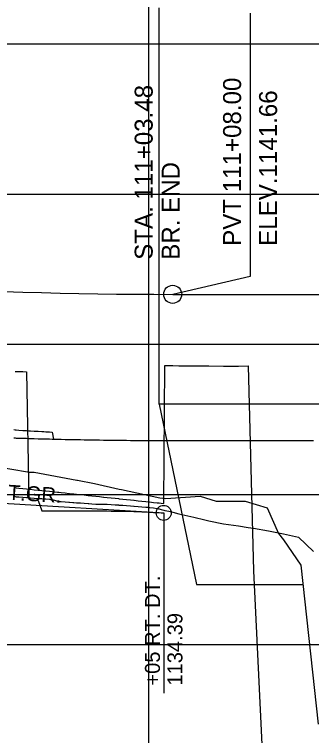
# Model space of a CAD drawing. Extents: x 688474 to 694748, y 765018 to 767373.
# Drawn here: x 692008.8 to 692107.9, y 765929.6 to 766169.7 of the extents above; entities that cross this region are included whole.
import ezdxf

# ---------------------------------------------------------------- set-up
doc = ezdxf.new("R2010")
doc.units = 0
for name, color, linetype in [('37', 7, 'Continuous'), ('BRIDGE', 7, 'Continuous'), ('R_Exist Surface', 7, 'Continuous'), ('R_Profile Work Left', 7, 'Continuous'), ('R_Profile Work Right', 7, 'Continuous'), ('R_Vert Alg', 7, 'Continuous'), ('R_Vert Alg Annot', 7, 'Continuous')]:
    doc.layers.add(name, color=color, linetype=linetype)

msp = doc.modelspace()

# ---------------------------------------------------------------- linework, layer by layer
at = {"layer": '37'}
for p, q in [((692053.59, 765809.92), (692053.59, 766359.92)), ((690853.59, 766159.92), (693453.59, 766159.92)), ((690853.59, 766109.92), (693453.59, 766109.92)), ((690853.59, 766059.92), (693453.59, 766059.92)), ((690853.59, 766009.92), (693453.59, 766009.92)), ((690853.59, 765959.92), (693453.59, 765959.92))]:
    msp.add_line(p, q, dxfattribs=at)
at = {"layer": 'BRIDGE'}
for p, q in [((692057.07, 766076.54), (692057.07, 766171.9)), ((692057.07, 766039.94), (692057.07, 766076.54)), ((692308.1, 766039.92), (692057.07, 766039.94)), ((692057.07, 766039.93), (692069.49, 765979.92)), ((692069.49, 765979.92), (692104.99, 765979.92))]:
    msp.add_line(p, q, dxfattribs=at)
at = {"layer": 'R_Exist Surface'}
msp.add_lwpolyline([(692000.61, 766019.59), (692013.83, 766017.31), (692015.39, 766017.32), (692029.58, 766014.68), (692029.87, 766014.67), (692035.49, 766013.58), (692043.77, 766011.69), (692044.49, 766011.59), (692057.34, 766008.76), (692059.3, 766008.51), (692070.73, 766009.33), (692076.14, 766007.7), (692085.77, 766007.66), (692093.07, 766005.48), (692096.83, 765996.91), (692098.54, 765994.77), (692104.27, 765986.41), (692110.15, 765933.44)], dxfattribs=at)
at = {"layer": 'R_Profile Work Left'}
for points in [[(692008.59, 766031.54), (692009.02, 766031.46), (692009.35, 766031.39), (692010.31, 766031.33), (692011.59, 766031.25), (692012.87, 766031.17), (692013.59, 766031.12), (692014.15, 766031.09), (692015.43, 766031.01), (692016.72, 766030.93), (692018, 766030.85), (692018.59, 766030.82), (692019.28, 766030.78), (692020.56, 766030.7), (692021.44, 766030.65), (692021.84, 766028.34), (692023.13, 766028.31), (692023.59, 766028.3), (692024.41, 766028.28), (692025.69, 766028.25), (692026.97, 766028.22), (692027.16, 766028.22), (692028.25, 766028.2), (692028.59, 766028.19), (692029.54, 766028.17), (692030.82, 766028.15), (692032.1, 766028.12), (692033.38, 766028.1), (692033.59, 766028.1), (692034.67, 766028.08), (692035.95, 766028.06), (692037.23, 766028.04), (692038.51, 766028.02), (692038.59, 766028.02), (692039.79, 766028), (692041.08, 766027.98), (692042.36, 766027.97), (692043.59, 766027.95), (692043.64, 766027.95), (692044.92, 766027.94), (692046.2, 766027.93), (692047.49, 766027.91), (692048.59, 766027.91), (692048.77, 766027.9), (692050.05, 766027.89), (692051.33, 766027.89), (692052.61, 766027.88), (692053.59, 766027.87), (692053.9, 766027.87), (692055.18, 766027.87), (692056.46, 766027.86), (692056.89, 766027.86), (692057.07, 766027.86), (692057.74, 766027.86), (692058.59, 766027.86), (692059.02, 766027.86), (692060.31, 766027.85), (692061.59, 766027.85), (692063.59, 766027.85), (692068.59, 766027.85), (692069.57, 766027.85), (692071.44, 766027.85), (692073.59, 766027.85), (692078.59, 766027.85), (692083.59, 766027.85), (692086.74, 766027.85), (692088.59, 766027.85), (692093.59, 766027.85), (692098.59, 766027.85), (692103.59, 766027.85), (692108.59, 766027.85)], [(692008.59, 766009.22), (692009.02, 766009.19), (692009.35, 766009.17), (692010.31, 766009.09), (692011.59, 766009), (692012.87, 766008.9), (692013.59, 766008.85), (692014.15, 766008.8), (692015.43, 766008.7), (692016.72, 766008.61), (692018, 766008.51), (692018.59, 766008.46), (692019.28, 766008.41), (692020.56, 766008.31), (692021.44, 766008.02), (692021.84, 766008.07), (692023.13, 766007.62), (692023.59, 766007.59), (692024.41, 766007.53), (692025.69, 766007.44), (692026.97, 766007.34), (692027.16, 766007.33), (692028.25, 766007.25), (692028.59, 766007.23), (692029.54, 766007.16), (692030.82, 766007.07), (692032.1, 766006.98), (692033.38, 766006.88), (692033.59, 766006.87), (692034.67, 766006.79), (692035.95, 766006.7), (692037.23, 766006.63), (692038.51, 766006.68), (692038.59, 766006.68), (692039.79, 766006.68), (692041.08, 766006.59), (692042.36, 766006.49), (692043.59, 766006.4), (692043.64, 766006.39), (692044.92, 766006.3), (692046.2, 766006.2), (692047.49, 766006.1), (692048.59, 766006.02), (692048.77, 766006), (692050.05, 766005.91), (692051.33, 766005.81), (692052.61, 766005.71), (692053.59, 766005.64), (692053.9, 766005.61), (692055.18, 766005.41), (692056.46, 766005.2), (692056.89, 766005.12), (692057.07, 766005.08), (692057.74, 766004.92), (692058.59, 766004.71), (692059.02, 766004.61), (692060.31, 766004.3), (692061.59, 766003.99), (692063.59, 766003.51), (692068.59, 766002.31), (692069.57, 766002.08), (692071.44, 766001.63), (692073.59, 766001.11), (692078.59, 766000.13), (692083.59, 765999.41), (692086.74, 765998.96), (692088.59, 765998.69), (692093.59, 765997.84), (692098.59, 765996.77), (692103.59, 765995.69), (692108.59, 765990.88)]]:
    msp.add_lwpolyline(points, dxfattribs=at)
at = {"layer": 'R_Profile Work Right'}
for points in [[(692058.59, 766006.92), (692059.02, 766052.81), (692060.31, 766052.8), (692061.59, 766052.79), (692063.59, 766052.77), (692068.59, 766052.73), (692069.57, 766052.72), (692071.44, 766052.7), (692073.59, 766052.69), (692078.59, 766052.65), (692083.59, 766052.64), (692086.74, 766052.68)], [(692086.74, 766052.68), (692088.59, 765984.46), (692093.59, 765880.56), (692098.59, 765883.29), (692103.59, 765885.82), (692108.59, 765887.81)], [(692009.02, 766050.87), (692009.35, 766050.86), (692010.31, 766050.84), (692011.59, 766050.8), (692012.87, 766050.77), (692013.59, 766008.3), (692014.15, 766008.22), (692015.43, 766008.07), (692016.72, 766007.92), (692018, 766004.41), (692018.59, 766004.41), (692019.28, 766004.41), (692020.56, 766004.42), (692021.44, 766004.42), (692021.84, 766004.42), (692023.13, 766004.42), (692023.59, 766004.43), (692024.41, 766004.45), (692025.69, 766004.45), (692026.97, 766004.46), (692027.16, 766004.46), (692028.25, 766004.47), (692028.59, 766004.47), (692029.54, 766004.47), (692030.82, 766004.48), (692032.1, 766004.48), (692033.38, 766004.51), (692033.59, 766004.51), (692034.67, 766004.5), (692035.95, 766004.48), (692037.23, 766004.46), (692038.51, 766004.44), (692038.59, 766004.44), (692039.79, 766004.42), (692041.08, 766004.4), (692042.36, 766004.39), (692043.59, 766004.37), (692043.64, 766004.37), (692044.92, 766004.35), (692046.2, 766004.33), (692047.49, 766004.31), (692048.59, 766004.26), (692048.77, 766004.25), (692050.05, 766004.19), (692051.33, 766004.14), (692052.61, 766004.08), (692053.59, 766004.03), (692053.9, 766004.02), (692055.18, 766003.95), (692056.46, 766003.89), (692056.89, 766003.86), (692057.07, 766003.85), (692057.74, 766003.82), (692058.59, 766003.78)], [(692008.59, 766028.72), (692009.02, 766028.71), (692009.35, 766028.7), (692010.31, 766028.66), (692011.59, 766028.62), (692012.87, 766028.59), (692013.59, 766028.56), (692014.15, 766028.55), (692015.43, 766028.51), (692016.72, 766028.47), (692018, 766028.44), (692018.59, 766028.42), (692019.28, 766028.41), (692020.56, 766028.37), (692021.44, 766028.35), (692021.84, 766028.34), (692023.13, 766028.31), (692023.59, 766028.3), (692024.41, 766028.28), (692025.69, 766028.25), (692026.97, 766028.22), (692027.16, 766028.22), (692028.25, 766028.2), (692028.59, 766028.19), (692029.54, 766028.17), (692030.82, 766028.15), (692032.1, 766028.12), (692033.38, 766028.1), (692033.59, 766028.09), (692034.67, 766028.08), (692035.95, 766028.06), (692037.23, 766028.04), (692038.51, 766028.02), (692038.59, 766028.02), (692039.79, 766028), (692041.08, 766027.98), (692042.36, 766027.97), (692043.59, 766027.95), (692043.64, 766027.95), (692044.92, 766027.94), (692046.2, 766027.93), (692047.49, 766027.91), (692048.59, 766027.9), (692048.77, 766027.9), (692050.05, 766027.89), (692051.33, 766027.89), (692052.61, 766027.88), (692053.59, 766027.87), (692053.9, 766027.87), (692055.18, 766027.87), (692056.46, 766027.86), (692056.89, 766027.86), (692057.07, 766027.86), (692057.74, 766027.86), (692058.59, 766027.86), (692059.02, 766027.85), (692060.31, 766027.85), (692061.59, 766027.85), (692063.59, 766027.85), (692068.59, 766027.85), (692069.57, 766027.85), (692071.44, 766027.85), (692073.59, 766027.85), (692078.59, 766027.85), (692083.59, 766027.85), (692086.74, 766027.85), (692088.59, 766027.85), (692093.59, 766027.85), (692098.59, 766027.85), (692103.59, 766027.85), (692108.59, 766027.85)], [(692009.02, 766012.17), (692009.35, 766012.14), (692010.31, 766012.04), (692011.59, 766011.9), (692012.87, 766011.77), (692013.59, 766011.69), (692014.15, 766011.63), (692015.43, 766011.49), (692016.72, 766011.36), (692018, 766011.22), (692018.59, 766011.16), (692019.28, 766011.09), (692020.56, 766010.95), (692021.44, 766010.86), (692021.84, 766010.81), (692023.13, 766010.68), (692023.59, 766010.63), (692024.41, 766010.54), (692025.69, 766010.41), (692026.97, 766010.27), (692027.16, 766010.25), (692028.25, 766010.14), (692028.59, 766010.1), (692029.54, 766010), (692030.82, 766009.86), (692032.1, 766009.73), (692033.38, 766009.59), (692033.59, 766009.57), (692034.67, 766009.46), (692035.95, 766009.32), (692037.23, 766009.18), (692038.51, 766009.05), (692038.59, 766009.04), (692039.79, 766008.91), (692041.08, 766008.78), (692042.36, 766008.64), (692043.59, 766008.51), (692043.64, 766008.5), (692044.92, 766008.37), (692046.2, 766008.23), (692047.49, 766008.1), (692048.59, 766007.98), (692048.77, 766007.96), (692050.05, 766007.83), (692051.33, 766007.69), (692052.61, 766007.55), (692053.59, 766007.45), (692053.9, 766007.42), (692055.18, 766007.28), (692056.46, 766007.15), (692056.89, 766007.1), (692057.07, 766007.08), (692057.74, 766007.01), (692058.59, 766006.92)]]:
    msp.add_lwpolyline(points, dxfattribs=at)
at = {"layer": 'R_Vert Alg'}
for p, q in [((692061.59, 766076.52), (692343.59, 766076.52)), ((691953.59, 766010.08), (692058.59, 766003.78))]:
    msp.add_line(p, q, dxfattribs=at)
msp.add_lwpolyline([(692005.34, 766077.5), (692011.59, 766077.29), (692017.84, 766077.11), (692024.09, 766076.95), (692030.34, 766076.82), (692036.59, 766076.71), (692042.84, 766076.63), (692049.09, 766076.57), (692055.34, 766076.53), (692061.59, 766076.52)], dxfattribs=at)
for centre, radius in [((692061.59, 766076.52), 3), ((692058.59, 766003.78), 2.5)]:
    msp.add_circle(centre, radius, dxfattribs=at)
at = {"layer": 'R_Vert Alg Annot'}
msp.add_line((692058.59, 766003.78), (692058.59, 765943.78), dxfattribs=at)
msp.add_lwpolyline([(692087.4, 766170.13), (692087.4, 766082.49), (692061.59, 766076.52)], dxfattribs=at)

# ---------------------------------------------------------------- texts
at = {"layer": 'BRIDGE'}
for s, p in [('STA. 111+03.48', (692054.92, 766088.02)), ('BR. END', (692063.92, 766088.02))]:
    msp.add_text(s, height=6, rotation=90, dxfattribs=at).set_placement(p)
at = {"layer": 'R_Vert Alg Annot'}
for s, height, rotation, p in [('PVT 111+08.00', 6, 90, (692084.4, 766092.67)), ('ELEV.1141.66', 6, 90, (692096.4, 766092.67)), ('-0.60% RT.DT.GR.', 5, 356.5641, (691967.98, 766010.47)), ('+05 RT. DT.', 5, 90, (692057.34, 765946.28)), ('1134.39', 5, 90, (692064.84, 765946.28))]:
    msp.add_text(s, height=height, rotation=rotation, dxfattribs=at).set_placement(p)

doc.saveas('drawing.dxf')
